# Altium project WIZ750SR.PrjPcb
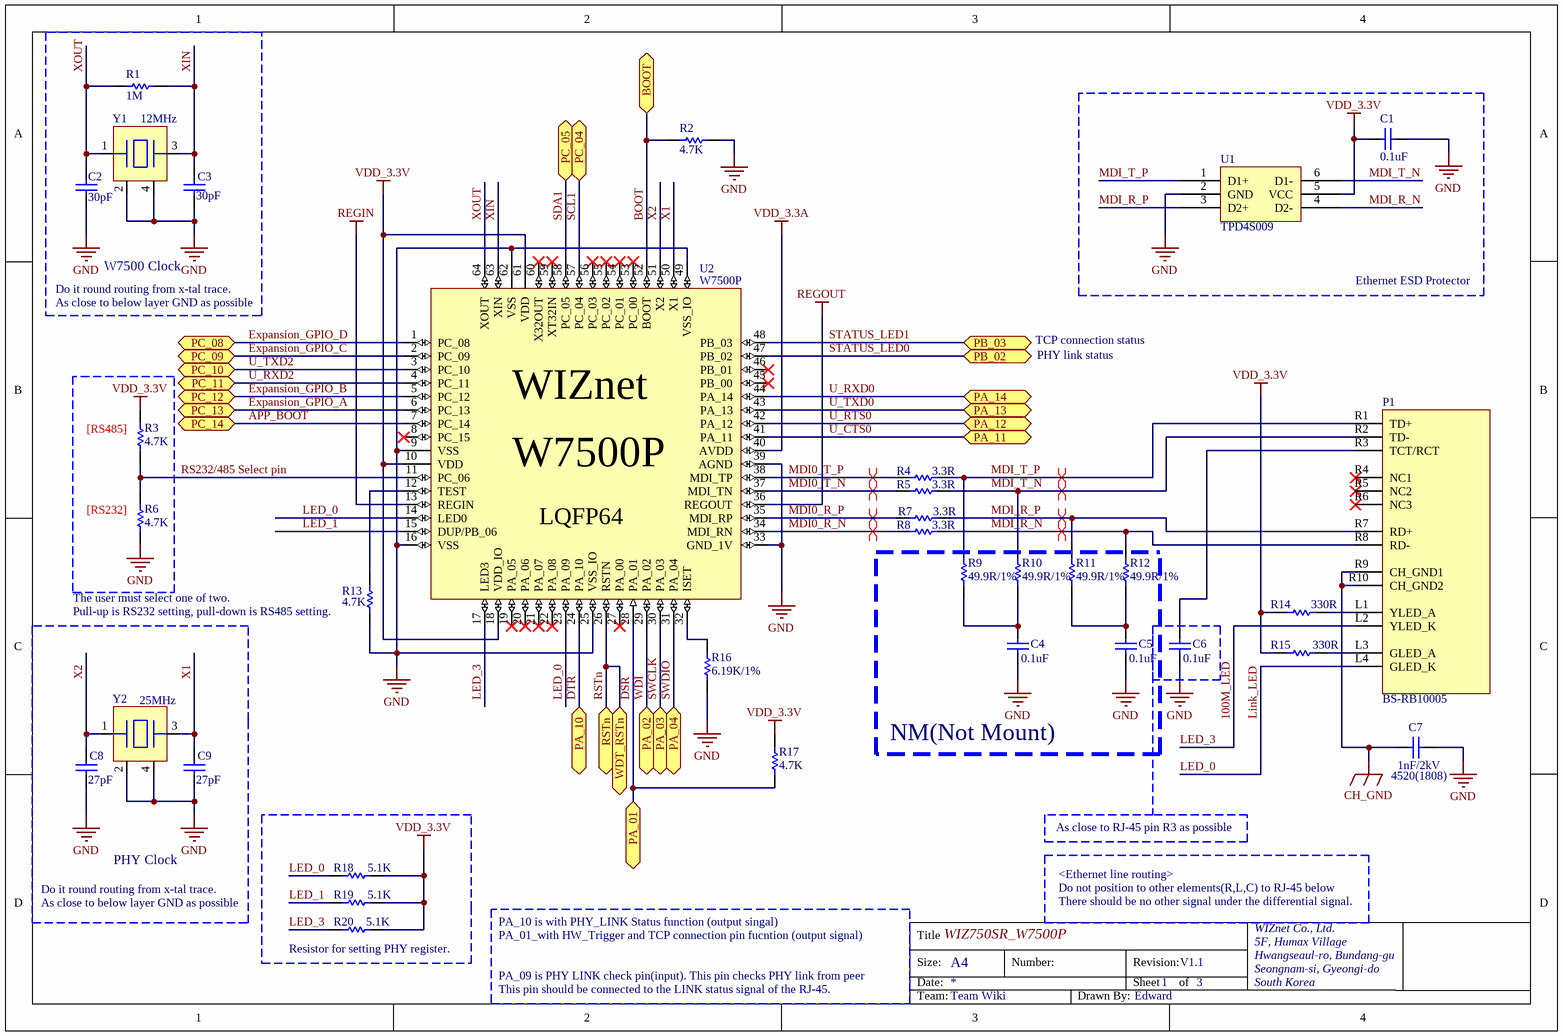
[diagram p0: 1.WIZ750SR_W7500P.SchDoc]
3 sheets, 92 parts. Net scope: flat (ports and power ports of the same name join across sheets).
Board file: WIZ750SR.PcbDoc
Sheets:
  1.WIZ750SR_W7500P.SchDoc
  2.WIZ750SR_Transceiver.SchDoc
  3.WIZ750SR_ETC.SchDoc

## Sheet 1.WIZ750SR_W7500P.SchDoc
size A4; DrawnBy: Peter; Organization: WIZnet Co., Ltd.; Address1: 5F, Humax Village; Address2: Hwangseaul-ro, Bundang-Gu; Address3: Seongnam-Si, Gyeonggi-Do; Address4: South Korea; Team: Wiki

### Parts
C1  0.1uF  [CAP-0402]
C2  30pF  [CAP-0402]
C3  30pF  [CAP-0402]
C4  0.1uF  [CAP-0402]
C5  0.1uF  [CAP-0402]
C6  0.1uF  [CAP-0402]
C7  1nF/2kV  [CAP-1808]
C8  27pF  [CAP-0402]
C9  27pF  [CAP-0402]
P1  BS-RB10005  [RJ45-125BAG1A]
R1  1M  [RES-0402]
R2  4.7K  [RES-0402]
R3  4.7K  [RES-0402]
R4  3.3R  [RES-0402]
R5  3.3R  [RES-0402]
R6  4.7K  [RES-0402]
R7  3.3R  [RES-0402]
R8  3.3R  [RES-0402]
R9  49.9R/1%  [RES-0402]
R10  49.9R/1%  [RES-0402]
R11  49.9R/1%  [RES-0402]
R12  49.9R/1%  [RES-0402]
R13  4.7K  [RES-0402]
R14  330R  [RES-0402]
R15  330R  [RES-0402]
R16  6.19K/1%  [RES-0402]
R17  4.7K  [RES-0402]
R18  5.1K  [RES-0402]
R19  5.1K  [RES-0402]
R20  5.1K  [RES-0402]
U1  TPD4S009  [SOT-23-6L]
U2  W7500P  [W7500-LQFP64]
Y1  12MHz  [OSC-TZ1067B]
Y2  25MHz  [OSC-82J0626]

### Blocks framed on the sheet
W7500 Clock: C2 C3 R1 Y1
Ethernet ESD Protector: C1 U1
PHY Clock: C8 C9 Y2

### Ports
BOOT, PA_01, PA_02, PA_03, PA_04, PA_10, PA_11, PA_12, PA_13, PA_14, PB_02, PB_03, PC_04, PC_05, PC_08, PC_09, PC_10, PC_11, PC_12, PC_13, PC_14, RSTn, WDT_RSTn

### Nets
CH_GND: C7.2 P1.R9(CH_GND1) P1.R10(CH_GND2)
GND: C1.1 C2.1 C3.1 C4.1 C5.1 C6.1 C7.1 C8.1 C9.1 R2.1 R6.1 R13.1 R16.1 U1.2(GND) U2.9(VSS) U2.16(VSS) U2.25(VSS_IO) U2.33(GND_1V) U2.39(AGND) U2.49(VSS_IO) U2.62(VSS) Y1.2 Y1.4 Y2.2 Y2.4
REGIN: U2.13(REGIN)
REGOUT: U2.36(REGOUT)
VDD_3.3A: U2.40(AVDD)
VDD_3.3V: C1.2 R3.2 R14.1 R15.1 R17.1 R18.2 R19.2 R20.2 U1.5(VCC) U2.10(VDD) U2.18(VDD_IO) U2.61(VDD)
100M_LED: P1.L2(YLED_K) R20.1 U2.17(LED3)  [also labelled LED_3]
APP_BOOT: U2.7(PC_14) ; port PC_14
BOOT: R2.2 U2.52(BOOT) ; port BOOT
DSR: R17.2 U2.28(PA_01) ; port PA_01
DTR: U2.24(PA_10) ; port PA_10
Expansion_GPIO_A: U2.6(PC_13) ; port PC_13
Expansion_GPIO_B: U2.5(PC_12) ; port PC_12
Expansion_GPIO_C: U2.2(PC_09) ; port PC_09
Expansion_GPIO_D: U2.1(PC_08) ; port PC_08
LED_0: P1.L4(GLED_K) R18.1 U2.14(LED0) U2.23(PA_09)  [also labelled Link_LED]
LED_1: R19.1 U2.15(DUP/PB_06)
MDI0_R_N: R8.1 U2.34(MDI_RN)
MDI0_R_P: R7.1 U2.35(MDI_RP)
MDI0_T_N: R5.1 U2.37(MDI_TN)
MDI0_T_P: R4.1 U2.38(MDI_TP)
MDI_R_N: P1.R8(RD-) R8.2 R12.2 U1.4(D2-)
MDI_R_P: P1.R7(RD+) R7.2 R11.2 U1.3(D2+)
MDI_T_N: P1.R2(TD-) R5.2 R10.2 U1.6(D1-)
MDI_T_P: P1.R1(TD+) R4.2 R9.2 U1.1(D1+)
RS232/485 Select pin: R3.1 R6.2 U2.11(PC_06)
RSTn: U2.26(RSTN) ; port RSTn, port WDT_RSTn
SCL1: U2.57(PC_04) ; port PC_04
SDA1: U2.58(PC_05) ; port PC_05
STATUS_LED0: U2.47(PB_02) ; port PB_02
STATUS_LED1: U2.48(PB_03) ; port PB_03
SWCLK: U2.30(PA_03) ; port PA_03
SWDIO: U2.31(PA_04) ; port PA_04
U_CTS0: U2.41(PA_11) ; port PA_11
U_RTS0: U2.42(PA_12) ; port PA_12  [project net 485_SEL]
U_RXD0: U2.44(PA_14) ; port PA_14  [project net RXD_RO]
U_RXD2: U2.4(PC_11) ; port PC_11
U_TXD0: U2.43(PA_13) ; port PA_13  [project net TXD_DI]
U_TXD2: U2.3(PC_10) ; port PC_10
WDI: U2.29(PA_02) ; port PA_02
X1: C9.2 U2.50(X1) Y2.3
X2: C8.2 U2.51(X2) Y2.1
XIN: C3.2 R1.2 U2.63(XIN) Y1.3
XOUT: C2.2 R1.1 U2.64(XOUT) Y1.1
NetC4_2: C4.2 R9.1 R10.1
NetC5_2: C5.2 R11.1 R12.1
NetC6_2: C6.2 P1.R3(TCT/RCT)
NetP1_L1: P1.L1(YLED_A) R14.2
NetP1_L3: P1.L3(GLED_A) R15.2
NetR13_2: R13.2 U2.12(TEST)
NetR16_2: R16.2 U2.32(ISET)

Not connected (* = marked no-connect by the designer): P1 R4(NC1)* R5(NC2)* R6(NC3)*; U2 8(PC_15)* 19(PA_05)* 20(PA_06)* 21(PA_07)* 22(PA_08)* 27(PA_00)* 45(PB_00)* 46(PB_01)* 53(PC_00)* 54(PC_01)* 55(PC_02)* 56(PC_03)* 59(XT32IN)* 60(X32OUT)*

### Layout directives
differential pair: MDI0_R_N, MDI0_R_P, MDI0_T_N, MDI0_T_P, MDI_R_N, MDI_R_P, MDI_T_N, MDI_T_P

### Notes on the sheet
- Do it round routing from x-tal trace.
- As close to below layer GND as possible
- TCP connection status
- PHY link status
- (near R3) [RS485]
- (near R6) [RS232]
- The user must select one of two.
- (near R13) Pull-up is RS232 setting, pull-down is RS485 setting.
- NM(Not Mount)
- (near C7) 4520(1808)
- As close to RJ-45 pin R3 as possible
- PA_10 is with PHY_LINK Status function (output singal)
- <Ethernet line routing>
- Do not position to other elements(R,L,C) to RJ-45 below
- There should be no other signal under the differential signal.
- (near R20) Resistor for setting PHY register.
- PA_09 is PHY LINK check pin(input). This pin checks PHY link from peer
- PA_01_with HW_Trigger and TCP connection pin fucntion (output signal)
- Title
- Size:
- Date:
- WIZ750SR_W7500P
- A4
- Number:
- Revision:
- Sheet
- 1
- of
- V1.1
- 3
- WIZnet Co., Ltd.
- 5F, Humax Village
- Hwangseaul-ro, Bundang-gu
- Seongnam-si, Gyeongi-do
- South Korea
- This pin should be connected to the LINK status signal of the RJ-45.
- Team:
- Team Wiki
- Drawn By:
- Edward

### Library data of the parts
C1-C6 C8 C9 = CAP-0402: Ceramic CAP 0402(1005)
C7 = CAP-1808: Ceramic CAP 1808(4520)
P1 = RB1-125BAG1A: 10/100 BASE-TX MAGJACK
R1-R20 = RES-0402
U1 = tpd4s009: 6-PIN SOT DBVor DCK Package
U2 = W7500P: WIZnet ARM Cortex-M0, Add PHY
Y1 = OSC-TZ1067B-12MHz: X-tal 12MHz,3.2x2.5 SMD, CL=20pF
Y2 = OSC-82J0626-25MHz: X-tal 25MHz,3.2x2.5 SMD, CL=18pF

## Sheet 2.WIZ750SR_Transceiver.SchDoc
size A4; DrawnBy: Peter; Organization: WIZnet Co., Ltd.; Address1: 5F, Humax Village; Address2: Hwangseaul-ro, Bundang-Gu; Address3: Seongnam-Si, Gyeonggi-Do; Address4: South Korea; Team: Wiki
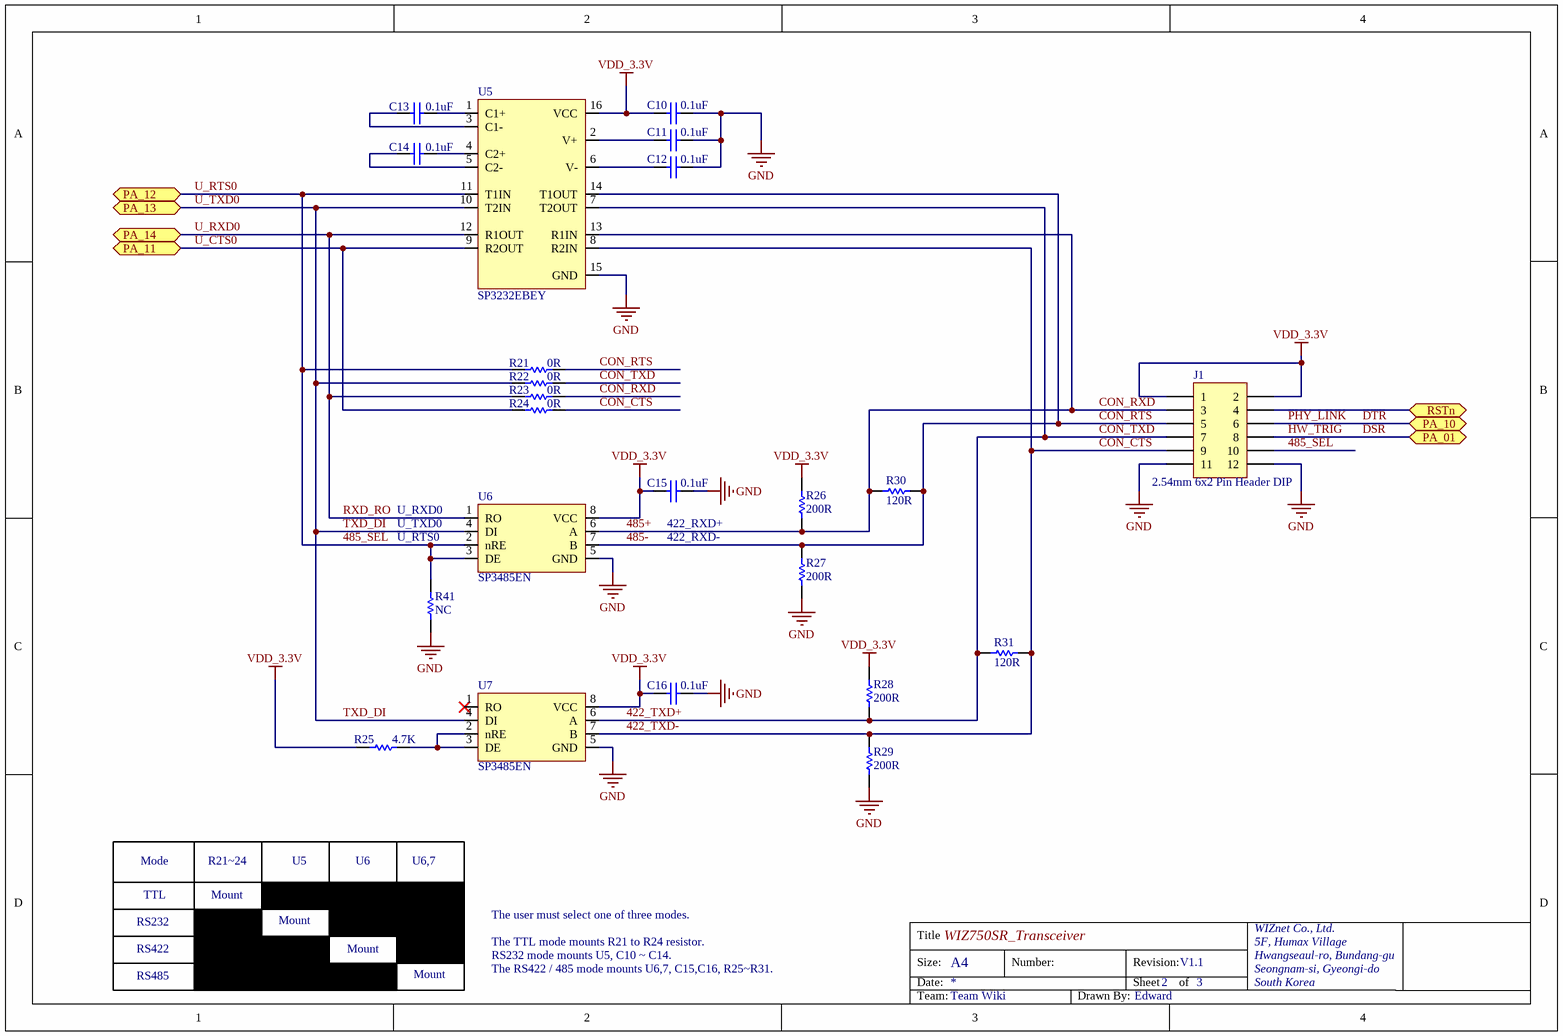
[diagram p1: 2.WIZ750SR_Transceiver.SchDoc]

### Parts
C10  0.1uF  [CAP-0402]
C11  0.1uF  [CAP-0402]
C12  0.1uF  [CAP-0402]
C13  0.1uF  [CAP-0402]
C14  0.1uF  [CAP-0402]
C15  0.1uF  [CAP-0402]
C16  0.1uF  [CAP-0402]
J1  2.54mm 6x2 Pin Header DIP  [IDC-2X6]
R21  0R  [RES-0402]
R22  0R  [RES-0402]
R23  0R  [RES-0402]
R24  0R  [RES-0402]
R25  4.7K  [RES-0402]
R26  200R  [RES-0402]
R27  200R  [RES-0402]
R28  200R  [RES-0402]
R29  200R  [RES-0402]
R30  120R  [RES-0402]
R31  120R  [RES-0402]
R41  NC  [RES-0402]
U5  SP3232EBEY  [TSSOP16(0.65/6.4)]
U6  SP3485EN  [SO-08]
U7  SP3485EN  [SO-08]

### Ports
PA_01, PA_10, PA_11, PA_12, PA_13, PA_14, RSTn

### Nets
GND: C10.1 C11.1 C12.1 C15.1 C16.1 J1.11 J1.12 R27.2 R29.2 R41.2 U5.15(GND) U6.5(GND) U7.5(GND)
VDD_3.3V: C10.2 C15.2 C16.2 J1.1 J1.2 R25.2 R26.1 R28.1 U5.16(VCC) U6.8(VCC) U7.8(VCC)
422_TXD+: J1.7 R22.1 R28.2 R31.2 U5.7(T2OUT) U7.6(A)  [also labelled CON_TXD]
422_TXD-: J1.9 R24.1 R29.1 R31.1 U5.8(R2IN) U7.7(B)  [also labelled CON_CTS]
485+: J1.3 R23.1 R26.2 R30.2 U5.13(R1IN) U6.6(A)  [also labelled CON_RXD]
485-: J1.5 R21.1 R27.1 R30.1 U5.14(T1OUT) U6.7(B)  [also labelled CON_RTS]
485_SEL: J1.10 R21.2 R41.1 U5.11(T1IN) U6.2(nRE) U6.3(DE) ; port PA_12  [also labelled U_RTS0]
DSR: J1.8 ; port PA_01  [also labelled HW_TRIG]
DTR: J1.6 ; port PA_10  [also labelled PHY_LINK]
RSTn: J1.4 ; port RSTn
RXD_RO: R23.2 U5.12(R1OUT) U6.1(RO) ; port PA_14  [also labelled U_RXD0]
TXD_DI: R22.2 U5.10(T2IN) U6.4(DI) U7.4(DI) ; port PA_13  [also labelled U_TXD0]
U_CTS0: R24.2 U5.9(R2OUT) ; port PA_11
NetC11_2: C11.2 U5.2(V+)
NetC12_2: C12.2 U5.6(V-)
NetC13_1: C13.1 U5.1(C1+)
NetC13_2: C13.2 U5.3(C1-)
NetC14_1: C14.1 U5.4(C2+)
NetC14_2: C14.2 U5.5(C2-)
NetR25_1: R25.1 U7.2(nRE) U7.3(DE)

Not connected (* = marked no-connect by the designer): U7 1(RO)*

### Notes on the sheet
- (near U6) U_RXD0
- U_TXD0
- U_RTS0
- (near C15) 422_RXD+
- (near C15) 422_RXD-
- RS232
- Mode
- TTL
- R21|4
- Mount
- U5
- U6
- U6,7
- The user must select one of three modes.
- RS422
- RS485
- The TTL mode mounts R21 to R24 resistor.
- RS232 mode mounts U5, C10 ~ C14.
- The RS422 / 485 mode mounts U6,7, C15,C16, R25~R31.
- Title
- Size:
- Date:
- WIZ750SR_Transceiver
- A4
- Number:
- Revision:
- Sheet
- 2
- of
- V1.1
- 3
- WIZnet Co., Ltd.
- 5F, Humax Village
- Hwangseaul-ro, Bundang-gu
- Seongnam-si, Gyeongi-do
- South Korea
- Team:
- Team Wiki
- Drawn By:
- Edward

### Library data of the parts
C10-C16 = CAP-0402: Ceramic CAP 0402(1005)
J1 = Header 6X2: Header, 6-Pin, Dual row
R21-R31 R41 = RES-0402
U5 = SP3232EBEY: True +3.0V to +5.5V RS-232 Transceivers TSSOP16
U6 U7 = SP3485EN: RS485 Transceiver

## Sheet 3.WIZ750SR_ETC.SchDoc
size A4; DrawnBy: Peter; Organization: WIZnet Co., Ltd.; Address1: 5F, Humax Village; Address2: Hwangseaul-ro, Bundang-Gu; Address3: Seongnam-Si, Gyeonggi-Do; Address4: South Korea; Team: Wiki
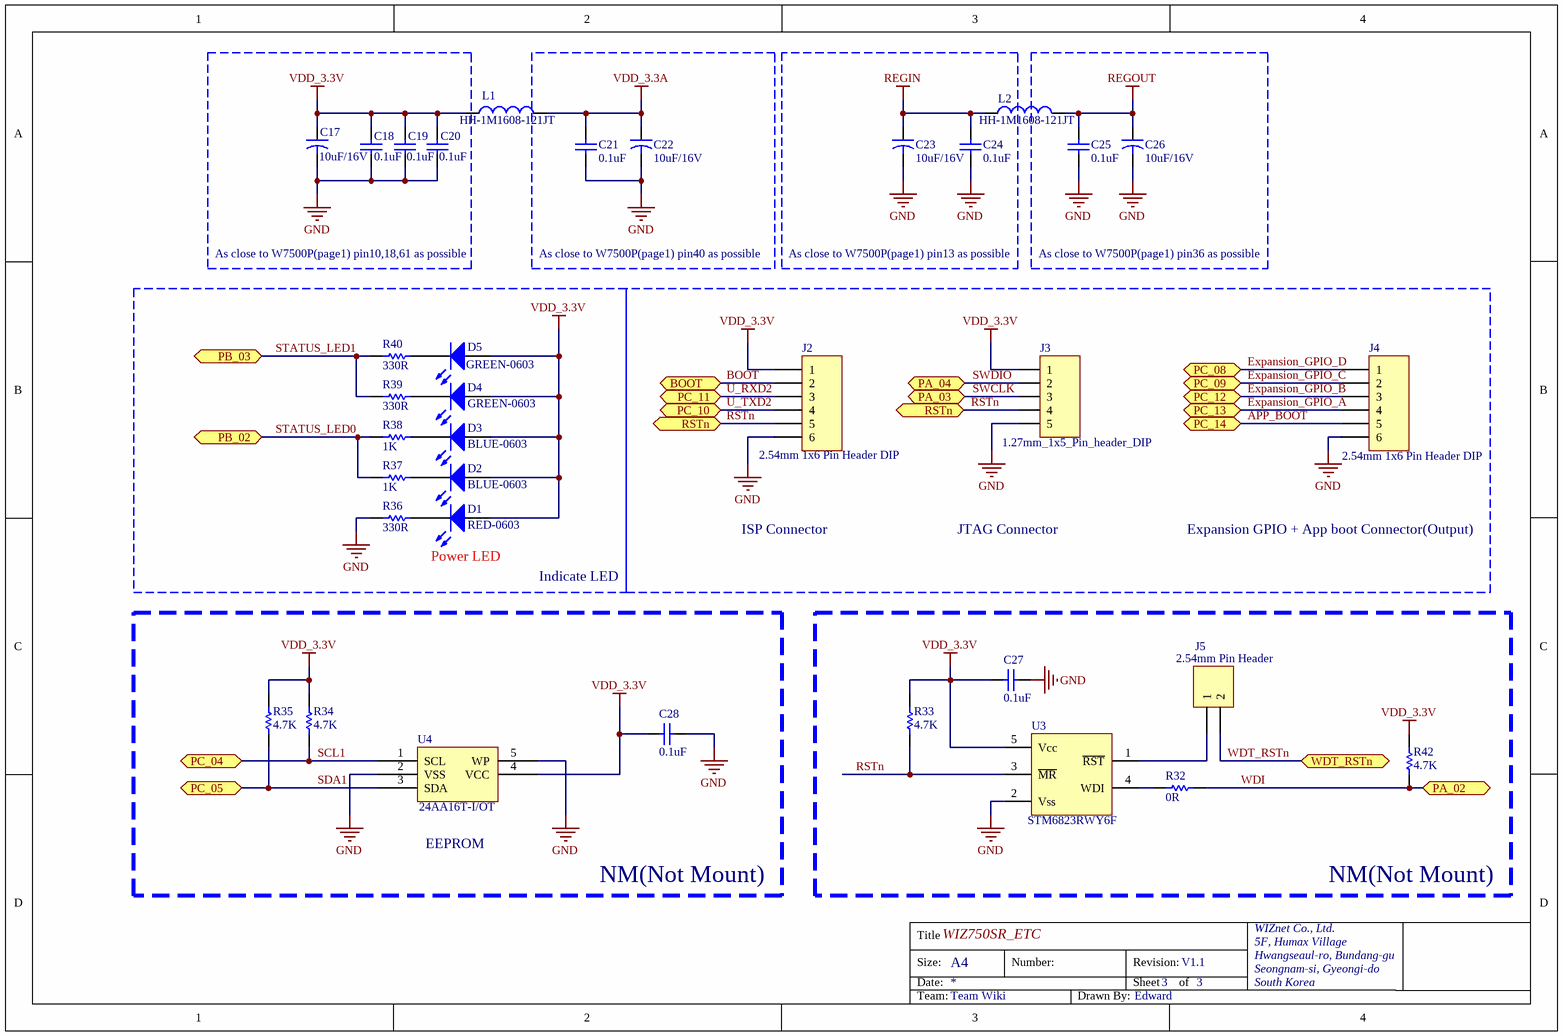
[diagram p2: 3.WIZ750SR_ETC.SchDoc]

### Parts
C17  10uF/16V  [CAP-A Size]
C18  0.1uF  [CAP-0402]
C19  0.1uF  [CAP-0402]
C20  0.1uF  [CAP-0402]
C21  0.1uF  [CAP-0402]
C22  10uF/16V  [CAP-A Size]
C23  10uF/16V  [CAP-A Size]
C24  0.1uF  [CAP-0402]
C25  0.1uF  [CAP-0402]
C26  10uF/16V  [CAP-A Size]
C27  0.1uF  [CAP-0402]
C28  0.1uF  [CAP-0402]
D1  RED-0603  [LED-0603-RED]
D2  BLUE-0603  [LED-0603-BLUE]
D3  BLUE-0603  [LED-0603-BLUE]
D4  GREEN-0603  [LED-0603-GREEN]
D5  GREEN-0603  [LED-0603-GREEN]
J2  2.54mm 1x6 Pin Header DIP  [IDC-1X6]
J3  1.27mm_1x5_Pin_header_DIP  [IDC-1X5(1.27MM)]
J4  2.54mm 1x6 Pin Header DIP  [IDC-1X6]
J5  2.54mm Pin Header  [IDC-1X2]
L1  HH-1M1608-121JT  [IND-0603]
L2  HH-1M1608-121JT  [IND-0603]
R32  0R  [RES-0402]
R33  4.7K  [RES-0402]
R34  4.7K  [RES-0402]
R35  4.7K  [RES-0402]
R36  330R  [RES-0402]
R37  1K  [RES-0402]
R38  1K  [RES-0402]
R39  330R  [RES-0402]
R40  330R  [RES-0402]
R42  4.7K  [RES-0402]
U3  STM6823RWY6F  [SOT-23-5L]
U4  24AA16T-I/OT  [SOT-23-5L]

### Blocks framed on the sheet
As close to W7500P(page1) pin10,18,61 as possible: C17-C20
As close to W7500P(page1) pin40 as possible: C21 C22
As close to W7500P(page1) pin13 as possible: C23 C24
As close to W7500P(page1) pin36 as possible: C25 C26
NM(Not Mount): C28 R34 R35 U4
NM(Not Mount): C27 J5 R32 R33 R42 U3

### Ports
BOOT, PA_02, PA_03, PA_04, PB_02, PB_03, PC_04, PC_05, PC_08, PC_09, PC_10, PC_11, PC_12, PC_13, PC_14, RSTn, WDT_RSTn

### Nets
GND: C17.2 C18.1 C19.1 C20.1 C21.1 C22.2 C23.2 C24.1 C25.1 C26.2 C27.1 C28.1 J2.6 J3.5 J4.6 R36.2 U3.2(Vss) U4.2(VSS) U4.5(WP)
REGIN: C23.1 C24.2 L2.1
REGOUT: C25.2 C26.1 L2.2
VDD_3.3A: C21.2 C22.1 L1.2
VDD_3.3V: C17.1 C18.2 C19.2 C20.2 C27.2 C28.2 D1.1(A) D2.1(A) D3.1(A) D4.1(A) D5.1(A) J2.1 J3.1 L1.1 R33.2 R34.2 R35.2 R42.1 U3.5(Vcc) U4.4(VCC)
APP_BOOT: J4.5 ; port PC_14
BOOT: J2.2 ; port BOOT
Expansion_GPIO_A: J4.4 ; port PC_13
Expansion_GPIO_B: J4.3 ; port PC_12
Expansion_GPIO_C: J4.2 ; port PC_09
Expansion_GPIO_D: J4.1 ; port PC_08
RSTn: J2.5 J3.4 J5.2 R33.1 U3.3(~{MR}) ; port RSTn, port WDT_RSTn  [also labelled WDT_RSTn]
SCL1: R34.1 U4.1(SCL) ; port PC_04
SDA1: R35.1 U4.3(SDA) ; port PC_05
STATUS_LED0: R37.2 R38.2 ; port PB_02
STATUS_LED1: R39.2 R40.2 ; port PB_03
SWCLK: J3.3 ; port PA_03
SWDIO: J3.2 ; port PA_04
U_RXD2: J2.3 ; port PC_11
U_TXD2: J2.4 ; port PC_10
WDI: R32.1 R42.2 ; port PA_02
NetD1_2: D1.2(K) R36.1
NetD2_2: D2.2(K) R37.1
NetD3_2: D3.2(K) R38.1
NetD4_2: D4.2(K) R39.1
NetD5_2: D5.2(K) R40.1
NetJ5_1: J5.1 U3.1(~{RST})
NetR32_2: R32.2 U3.4(WDI)

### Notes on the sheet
- Power LED
- Indicate LED
- ISP Connector
- JTAG Connector
- Expansion GPIO + App boot Connector(Output)
- (near U4) EEPROM
- Title
- Size:
- Date:
- WIZ750SR_ETC
- A4
- Number:
- Revision:
- Sheet
- 3
- of
- V1.1
- WIZnet Co., Ltd.
- 5F, Humax Village
- Hwangseaul-ro, Bundang-gu
- Seongnam-si, Gyeongi-do
- South Korea
- Team:
- Team Wiki
- Drawn By:
- Edward

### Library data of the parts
C17 C22 C23 C26 = CAP-A Size: Tantla CAP A Size EIA/IECQ 3216
C18-C21 C24 C25 C27 C28 = CAP-0402: Ceramic CAP 0402(1005)
D1-D5 = LED-0603
J2 J4 = Header 6: Header, 6-Pin
J5 = Header 2: Header, 2-Pin
L1 L2 = IND-0603: Inductor 0603(1608)
R32-R40 R42 = RES-0402
U3 = STM6823: Manual_Reset SOT23-5
U4 = 24AAxxT-i-OT: SOT-23

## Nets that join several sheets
GND: 1.WIZ750SR_W7500P (25 pins), 2.WIZ750SR_Transceiver (13 pins), 3.WIZ750SR_ETC (19 pins)
REGIN: 1.WIZ750SR_W7500P (U2.13), 3.WIZ750SR_ETC (C23.1 C24.2 L2.1)
REGOUT: 1.WIZ750SR_W7500P (U2.36), 3.WIZ750SR_ETC (C25.2 C26.1 L2.2)
VDD_3.3A: 1.WIZ750SR_W7500P (U2.40), 3.WIZ750SR_ETC (C21.2 C22.1 L1.2)
VDD_3.3V: 1.WIZ750SR_W7500P (12 pins), 2.WIZ750SR_Transceiver (11 pins), 3.WIZ750SR_ETC (20 pins)
485_SEL: 1.WIZ750SR_W7500P (U2.42), 2.WIZ750SR_Transceiver (6 pins)
APP_BOOT: 1.WIZ750SR_W7500P (U2.7), 3.WIZ750SR_ETC (J4.5)
BOOT: 1.WIZ750SR_W7500P (R2.2 U2.52), 3.WIZ750SR_ETC (J2.2)
DSR: 1.WIZ750SR_W7500P (R17.2 U2.28), 2.WIZ750SR_Transceiver (J1.8)
DTR: 1.WIZ750SR_W7500P (U2.24), 2.WIZ750SR_Transceiver (J1.6)
Expansion_GPIO_A: 1.WIZ750SR_W7500P (U2.6), 3.WIZ750SR_ETC (J4.4)
Expansion_GPIO_B: 1.WIZ750SR_W7500P (U2.5), 3.WIZ750SR_ETC (J4.3)
Expansion_GPIO_C: 1.WIZ750SR_W7500P (U2.2), 3.WIZ750SR_ETC (J4.2)
Expansion_GPIO_D: 1.WIZ750SR_W7500P (U2.1), 3.WIZ750SR_ETC (J4.1)
RSTn: 1.WIZ750SR_W7500P (U2.26), 2.WIZ750SR_Transceiver (J1.4), 3.WIZ750SR_ETC (5 pins)
RXD_RO: 1.WIZ750SR_W7500P (U2.44), 2.WIZ750SR_Transceiver (R23.2 U5.12 U6.1)
SCL1: 1.WIZ750SR_W7500P (U2.57), 3.WIZ750SR_ETC (R34.1 U4.1)
SDA1: 1.WIZ750SR_W7500P (U2.58), 3.WIZ750SR_ETC (R35.1 U4.3)
STATUS_LED0: 1.WIZ750SR_W7500P (U2.47), 3.WIZ750SR_ETC (R37.2 R38.2)
STATUS_LED1: 1.WIZ750SR_W7500P (U2.48), 3.WIZ750SR_ETC (R39.2 R40.2)
SWCLK: 1.WIZ750SR_W7500P (U2.30), 3.WIZ750SR_ETC (J3.3)
SWDIO: 1.WIZ750SR_W7500P (U2.31), 3.WIZ750SR_ETC (J3.2)
TXD_DI: 1.WIZ750SR_W7500P (U2.43), 2.WIZ750SR_Transceiver (R22.2 U5.10 U6.4 U7.4)
U_CTS0: 1.WIZ750SR_W7500P (U2.41), 2.WIZ750SR_Transceiver (R24.2 U5.9)
U_RXD2: 1.WIZ750SR_W7500P (U2.4), 3.WIZ750SR_ETC (J2.3)
U_TXD2: 1.WIZ750SR_W7500P (U2.3), 3.WIZ750SR_ETC (J2.4)
WDI: 1.WIZ750SR_W7500P (U2.29), 3.WIZ750SR_ETC (R32.1 R42.2)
